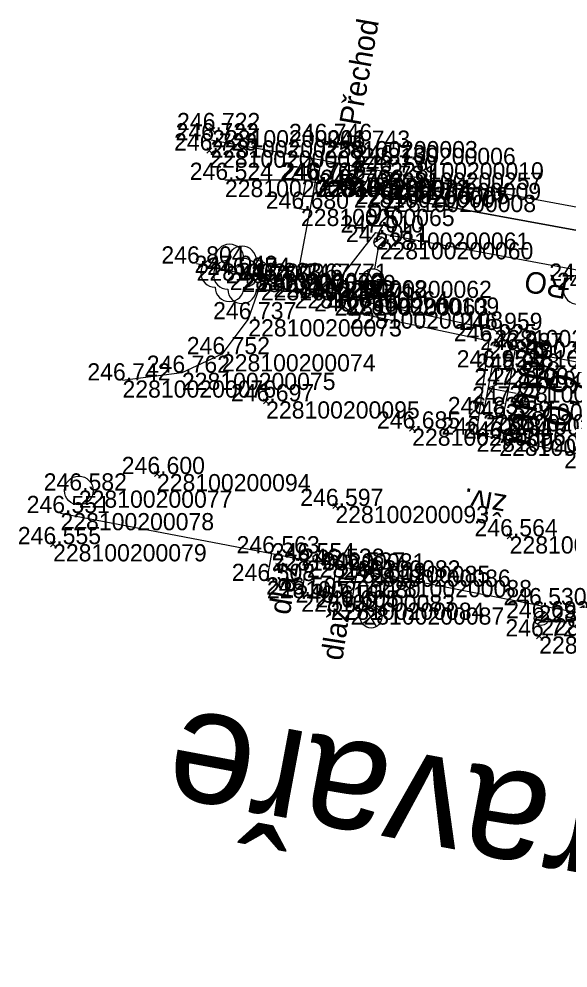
# Model space of a CAD drawing. Extents: x -489477 to -488834, y -1088874 to -1088756.
# Drawn here: x -489210.7 to -489172.4, y -1088873.7 to -1088807.5 of the extents above; entities that cross this region are included whole.
import ezdxf

# ---------------------------------------------------------------- set-up
doc = ezdxf.new("R2010")
doc.units = 0
for name, color, linetype in [('Vrstva 1', 7, 'Continuous'), ('Vrstva 12', 7, 'Continuous'), ('Vrstva 14', 7, 'Continuous'), ('Vrstva 16', 7, 'Continuous'), ('Vrstva 17', 7, 'Continuous'), ('Vrstva 23', 7, 'Continuous'), ('Vrstva 25', 7, 'Continuous'), ('Vrstva 36', 7, 'Continuous'), ('Vrstva 4', 7, 'Continuous'), ('Vrstva 43', 7, 'Continuous'), ('Vrstva 49', 7, 'Continuous'), ('Vrstva 50', 7, 'Continuous'), ('Vrstva 51', 7, 'Continuous'), ('Vrstva 60', 7, 'Continuous'), ('Vrstva 61', 7, 'Continuous')]:
    doc.layers.add(name, color=color, linetype=linetype)

msp = doc.modelspace()

# ---------------------------------------------------------------- linework, layer by layer
at = {"layer": 'Vrstva 1'}
msp.add_lwpolyline([(-489069.54, -1088836.646), (-489079.744, -1088835.745), (-489092.96, -1088834.275), (-489107.116, -1088832.285), (-489121.051, -1088829.933), (-489135.033, -1088827.388), (-489147.694, -1088825.064), (-489168.943, -1088821.148), (-489184.879, -1088818.208), (-489197.298, -1088815.961)], dxfattribs=at)
at = {"layer": 'Vrstva 12'}
msp.add_line((-489176.005, -1088833.62), (-489177.97, -1088833.248), dxfattribs=at)
for points in [[(-489176.316, -1088832.043), (-489177.696, -1088831.8), (-489178.314, -1088835.061), (-489176.925, -1088835.313), (-489176.725, -1088834.325), (-489176.475, -1088833.048), (-489176.316, -1088832.043)], [(-489177.423, -1088833.046), (-489177.97, -1088833.248), (-489177.535, -1088833.636)]]:
    msp.add_lwpolyline(points, dxfattribs=at)
at = {"layer": 'Vrstva 14'}
msp.add_lwpolyline([(-489187.318, -1088819.458), (-489185.323, -1088819.766), (-489169.302, -1088822.686), (-489155.292, -1088825.292), (-489153.303, -1088825.681), (-489149.813, -1088826.322), (-489147.827, -1088826.686), (-489135.3, -1088829.033), (-489121.345, -1088831.585), (-489107.306, -1088833.925), (-489093.168, -1088835.915), (-489080.034, -1088837.349), (-489069.629, -1088838.273)], dxfattribs=at)
at = {"layer": 'Vrstva 16'}
for points in [[(-489169.302, -1088822.686), (-489185.323, -1088819.766), (-489187.318, -1088819.458), (-489187.195, -1088819.208), (-489189.849, -1088818.713), (-489189.998, -1088818.713), (-489191.448, -1088826.485), (-489188.658, -1088826.988), (-489188.408, -1088825.755), (-489185.794, -1088822.393), (-489168.742, -1088825.545)], [(-489169.396, -1088838.257), (-489177.179, -1088836.771), (-489178.765, -1088836.485), (-489177.893, -1088829.979), (-489187.632, -1088827.897), (-489188.658, -1088826.988), (-489191.448, -1088826.485), (-489193.797, -1088825.924), (-489194.677, -1088828.441), (-489196.517, -1088830.877), (-489199.306, -1088832.173), (-489203.448, -1088832.708)], [(-489207.771, -1088841.957), (-489193.044, -1088844.767), (-489190.594, -1088845.255), (-489188.527, -1088845.637), (-489187.095, -1088845.9), (-489174.443, -1088848.384), (-489164.096, -1088850.294)], [(-489193.374, -1088846.695), (-489193.044, -1088844.767), (-489190.594, -1088845.255), (-489190.979, -1088847.638)], [(-489188.928, -1088848.205), (-489188.527, -1088845.637), (-489187.095, -1088845.9), (-489187.543, -1088848.539)]]:
    msp.add_lwpolyline(points, dxfattribs=at)
at = {"layer": 'Vrstva 17'}
msp.add_line((-489198.284, -1088824.555), (-489192.926, -1088825.715), dxfattribs=at)
msp.add_lwpolyline([(-489187.894, -1088826.922), (-489177.514, -1088829.188), (-489176.061, -1088830.595)], dxfattribs=at)
at = {"layer": 'Vrstva 23'}
msp.add_lwpolyline([(-489169.396, -1088838.257), (-489177.179, -1088836.771), (-489176.925, -1088835.313), (-489176.725, -1088834.325), (-489176.475, -1088833.048), (-489176.316, -1088832.043), (-489176.061, -1088830.595), (-489169.904, -1088831.752)], dxfattribs=at)
at = {"layer": 'Vrstva 25'}
for p, q in [((-489185.328, -1088822.714), (-489185.911, -1088823.115)), ((-489185.861, -1088824.931), (-489185.589, -1088823.456)), ((-489185.119, -1088823.055), (-489185.665, -1088823.431)), ((-489185.404, -1088825.211), (-489186.591, -1088826.123)), ((-489185.606, -1088826.305), (-489186.389, -1088825.029)), ((-489185.421, -1088846.279), (-489186.008, -1088846.674)), ((-489185.215, -1088846.622), (-489185.765, -1088846.992)), ((-489185.978, -1088848.49), (-489185.689, -1088847.019)), ((-489185.524, -1088848.776), (-489186.721, -1088849.674)), ((-489185.738, -1088849.867), (-489186.507, -1088848.583))]:
    msp.add_line(p, q, dxfattribs=at)
for centre, radius in [((-489185.516, -1088823.063), 0.4), ((-489185.997, -1088825.667), 0.749), ((-489185.612, -1088846.626), 0.4), ((-489186.122, -1088849.225), 0.749)]:
    msp.add_circle(centre, radius, dxfattribs=at)
at = {"layer": 'Vrstva 36'}
for p, q in [((-489173.967, -1088848.888), (-489174.736, -1088849.405)), ((-489173.764, -1088849.203), (-489174.523, -1088849.713))]:
    msp.add_line(p, q, dxfattribs=at)
msp.add_circle((-489174.252, -1088849.295), 0.5, dxfattribs=at)
at = {"layer": 'Vrstva 4'}
for points in [[(-489189.849, -1088818.713), (-489187.195, -1088819.208), (-489186.743, -1088816.479), (-489189.39, -1088816.011), (-489189.849, -1088818.713)], [(-489196.307, -1088818.721), (-489189.998, -1088818.713), (-489189.849, -1088818.713)]]:
    msp.add_lwpolyline(points, dxfattribs=at)
at = {"layer": 'Vrstva 43'}
msp.add_circle((-489206.492, -1088840.386), 1, dxfattribs=at)
at = {"layer": 'Vrstva 49'}
for p, q in [((-489197.372, -1088815.073), (-489197.018, -1088815.427)), ((-489197.372, -1088815.427), (-489197.018, -1088815.073)), ((-489197.578, -1088816.495), (-489197.224, -1088816.849)), ((-489197.578, -1088816.849), (-489197.224, -1088816.495)), ((-489184.963, -1088817.315), (-489184.609, -1088817.669)), ((-489184.963, -1088817.669), (-489184.609, -1088817.315)), ((-489185.15, -1088818.748), (-489184.796, -1088819.102)), ((-489185.15, -1088819.102), (-489184.796, -1088818.748)), ((-489193.612, -1088833.988), (-489193.258, -1088834.342)), ((-489193.612, -1088834.342), (-489193.258, -1088833.988)), ((-489183.429, -1088835.887), (-489183.075, -1088836.241)), ((-489183.429, -1088836.241), (-489183.075, -1088835.887)), ((-489201.225, -1088839.06), (-489200.871, -1088839.414)), ((-489201.225, -1088839.414), (-489200.871, -1088839.06)), ((-489188.784, -1088841.285), (-489188.43, -1088841.639)), ((-489188.784, -1088841.639), (-489188.43, -1088841.285)), ((-489176.634, -1088843.403), (-489176.28, -1088843.757)), ((-489176.634, -1088843.757), (-489176.28, -1088843.403)), ((-489208.464, -1088843.95), (-489208.11, -1088844.304)), ((-489208.464, -1088844.304), (-489208.11, -1088843.95)), ((-489174.575, -1088850.385), (-489174.221, -1088850.739)), ((-489174.575, -1088850.739), (-489174.221, -1088850.385))]:
    msp.add_line(p, q, dxfattribs=at)
at = {"layer": 'Vrstva 50'}
for p, q in [((-489196.045, -1088825.209), (-489195.903, -1088825.209)), ((-489195.17, -1088825.343), (-489195.028, -1088825.343))]:
    msp.add_line(p, q, dxfattribs=at)
for centre, start, end in [((-489195.985, -1088824.207), 0, 180), ((-489195.11, -1088824.341), 0, 180), ((-489196.985, -1088825.207), 90, 270), ((-489194.985, -1088825.207), 270, 90), ((-489196.11, -1088825.341), 90, 270), ((-489194.11, -1088825.341), 270, 90), ((-489171.713, -1088826.394), 90, 270), ((-489195.985, -1088826.207), 180, 0), ((-489195.11, -1088826.341), 180, 0)]:
    msp.add_arc(centre, 1, start, end, dxfattribs=at)
at = {"layer": 'Vrstva 51'}
msp.add_line((-489191.497, -1088820.65), (-489190.513, -1088820.828), dxfattribs=at)
msp.add_lwpolyline([(-489191.005, -1088820.739), (-489190.649, -1088818.771), (-489189.665, -1088818.949), (-489190.337, -1088817.049), (-489191.633, -1088818.593), (-489190.649, -1088818.771)], dxfattribs=at)
at = {"layer": 'Vrstva 60'}
for p, q in [((-489197.195, -1088815.25), (-489197.195, -1088815.25)), ((-489197.298, -1088815.961), (-489197.298, -1088815.961)), ((-489189.39, -1088816.011), (-489189.39, -1088816.011)), ((-489197.401, -1088816.672), (-489197.401, -1088816.672)), ((-489186.743, -1088816.479), (-489186.743, -1088816.479)), ((-489184.786, -1088817.492), (-489184.786, -1088817.492)), ((-489184.879, -1088818.208), (-489184.879, -1088818.208)), ((-489196.307, -1088818.721), (-489196.307, -1088818.721)), ((-489189.998, -1088818.713), (-489189.998, -1088818.713)), ((-489189.849, -1088818.713), (-489189.849, -1088818.713)), ((-489184.973, -1088818.925), (-489184.973, -1088818.925)), ((-489187.318, -1088819.458), (-489187.318, -1088819.458)), ((-489187.195, -1088819.208), (-489187.195, -1088819.208)), ((-489185.323, -1088819.766), (-489185.323, -1088819.766)), ((-489191.005, -1088820.739), (-489191.005, -1088820.739)), ((-489185.794, -1088822.393), (-489185.794, -1088822.393)), ((-489185.516, -1088823.063), (-489185.516, -1088823.063)), ((-489198.284, -1088824.555), (-489198.284, -1088824.555)), ((-489195.974, -1088825.209), (-489195.974, -1088825.209)), ((-489195.099, -1088825.343), (-489195.099, -1088825.343)), ((-489193.797, -1088825.924), (-489193.797, -1088825.924)), ((-489192.926, -1088825.715), (-489192.926, -1088825.715)), ((-489188.408, -1088825.755), (-489188.408, -1088825.755)), ((-489191.448, -1088826.485), (-489191.448, -1088826.485)), ((-489187.894, -1088826.922), (-489187.894, -1088826.922)), ((-489188.658, -1088826.988), (-489188.658, -1088826.988)), ((-489187.632, -1088827.897), (-489187.632, -1088827.897)), ((-489194.677, -1088828.441), (-489194.677, -1088828.441)), ((-489177.514, -1088829.188), (-489177.514, -1088829.188)), ((-489177.893, -1088829.979), (-489177.893, -1088829.979)), ((-489196.517, -1088830.877), (-489196.517, -1088830.877)), ((-489176.061, -1088830.595), (-489176.061, -1088830.595)), ((-489199.306, -1088832.173), (-489199.306, -1088832.173)), ((-489177.696, -1088831.8), (-489177.696, -1088831.8)), ((-489176.316, -1088832.043), (-489176.316, -1088832.043)), ((-489203.448, -1088832.708), (-489203.448, -1088832.708)), ((-489176.475, -1088833.048), (-489176.475, -1088833.048)), ((-489193.435, -1088834.165), (-489193.435, -1088834.165)), ((-489176.725, -1088834.325), (-489176.725, -1088834.325)), ((-489178.314, -1088835.061), (-489178.314, -1088835.061)), ((-489176.925, -1088835.313), (-489176.925, -1088835.313)), ((-489183.252, -1088836.064), (-489183.252, -1088836.064)), ((-489178.765, -1088836.485), (-489178.765, -1088836.485)), ((-489177.179, -1088836.771), (-489177.179, -1088836.771)), ((-489201.048, -1088839.237), (-489201.048, -1088839.237)), ((-489206.492, -1088840.386), (-489206.492, -1088840.386)), ((-489188.607, -1088841.462), (-489188.607, -1088841.462)), ((-489207.771, -1088841.957), (-489207.771, -1088841.957)), ((-489208.287, -1088844.127), (-489208.287, -1088844.127)), ((-489176.457, -1088843.58), (-489176.457, -1088843.58)), ((-489193.044, -1088844.767), (-489193.044, -1088844.767)), ((-489190.594, -1088845.255), (-489190.594, -1088845.255)), ((-489188.527, -1088845.637), (-489188.527, -1088845.637)), ((-489187.095, -1088845.9), (-489187.095, -1088845.9)), ((-489193.374, -1088846.695), (-489193.374, -1088846.695)), ((-489185.612, -1088846.626), (-489185.612, -1088846.626)), ((-489190.979, -1088847.638), (-489190.979, -1088847.638)), ((-489188.928, -1088848.205), (-489188.928, -1088848.205)), ((-489187.543, -1088848.539), (-489187.543, -1088848.539)), ((-489174.443, -1088848.384), (-489174.443, -1088848.384)), ((-489174.252, -1088849.295), (-489174.252, -1088849.295)), ((-489174.398, -1088850.562), (-489174.398, -1088850.562))]:
    msp.add_line(p, q, dxfattribs=at)

# ---------------------------------------------------------------- texts
at = {"layer": 'Vrstva 12'}
for s, p in [('rampa', (-489175.062, -1088837.372)), ('0,9', (-489172.292, -1088836.093))]:
    msp.add_text(s, height=2, rotation=79.269, dxfattribs=at).set_placement(p)
at = {"layer": 'Vrstva 16'}
for s, rotation, p in [('živ.', 170.01125, (-489176.602, -1088840.719)), ('dlaž.', 80.28727, (-489191.787, -1088849.112)), ('dlaž.', 81.12479, (-489188.13, -1088852.298))]:
    msp.add_text(s, height=1.5, rotation=rotation, dxfattribs=at).set_placement(p)
at = {"layer": 'Vrstva 23'}
msp.add_text('žst.Kravaře', height=8, rotation=169.39925, dxfattribs=at).set_placement((-489146.368, -1088865.517))
at = {"layer": 'Vrstva 25'}
for s, p in [('S6', (-489183.889, -1088820.717)), ('RO', (-489172.303, -1088825.575))]:
    msp.add_text(s, height=1.5, rotation=169.52729, dxfattribs=at).set_placement(p)
at = {"layer": 'Vrstva 4'}
msp.add_text('Přechod', height=1.5, rotation=79.9735, dxfattribs=at).set_placement((-489186.868, -1088814.997))
at = {"layer": 'Vrstva 60'}
for s, p in [('228100200001', (-489197.195, -1088816.45)), ('228100200256', (-489197.298, -1088817.161)), ('228100200003', (-489189.39, -1088817.211)), ('228100200002', (-489197.401, -1088817.872)), ('228100200006', (-489186.743, -1088817.679)), ('228100200010', (-489184.786, -1088818.692)), ('228100200257', (-489184.879, -1088819.408)), ('228100200066', (-489196.307, -1088819.921)), ('228100200072', (-489189.998, -1088819.913)), ('228100200004', (-489189.849, -1088819.913)), ('228100200009', (-489184.973, -1088820.125)), ('228100200007', (-489187.318, -1088820.658)), ('228100200005', (-489187.195, -1088820.408)), ('228100200008', (-489185.323, -1088820.966)), ('228100200065', (-489191.005, -1088821.939)), ('228100200061', (-489185.794, -1088823.593)), ('228100200060', (-489185.516, -1088824.263)), ('228100200067', (-489198.284, -1088825.755)), ('228100200070', (-489195.974, -1088826.409)), ('228100200069', (-489195.099, -1088826.543)), ('228100200071', (-489193.797, -1088827.124)), ('228100200068', (-489192.926, -1088826.915)), ('228100200062', (-489188.408, -1088826.955)), ('228100200064', (-489191.448, -1088827.685)), ('228100200109', (-489187.894, -1088828.122)), ('228100200063', (-489188.658, -1088828.188)), ('228100200108', (-489187.632, -1088829.097)), ('228100200073', (-489194.677, -1088829.641)), ('228100200106', (-489177.514, -1088830.388)), ('228100200107', (-489177.893, -1088831.179)), ('228100200074', (-489196.517, -1088832.077)), ('228100200105', (-489176.061, -1088831.795)), ('228100200075', (-489199.306, -1088833.373)), ('228100200101', (-489177.696, -1088833)), ('228100200102', (-489176.316, -1088833.243)), ('228100200076', (-489203.448, -1088833.908)), ('228100200103', (-489176.475, -1088834.248)), ('228100200095', (-489193.435, -1088835.365)), ('228100200104', (-489176.725, -1088835.525)), ('228100200099', (-489178.314, -1088836.261)), ('228100200100', (-489176.925, -1088836.513)), ('228100200096', (-489183.252, -1088837.264)), ('228100200097', (-489178.765, -1088837.685)), ('228100200098', (-489177.179, -1088837.971)), ('228100200094', (-489201.048, -1088840.437)), ('228100200077', (-489206.492, -1088841.586)), ('228100200093', (-489188.607, -1088842.662)), ('228100200078', (-489207.771, -1088843.157)), ('228100200079', (-489208.287, -1088845.327)), ('228100200092', (-489176.457, -1088844.78)), ('228100200081', (-489193.044, -1088845.967)), ('228100200082', (-489190.594, -1088846.455)), ('228100200085', (-489188.527, -1088846.837)), ('228100200086', (-489187.095, -1088847.1)), ('228100200080', (-489193.374, -1088847.895)), ('228100200088', (-489185.612, -1088847.826)), ('228100200083', (-489190.979, -1088848.838)), ('228100200084', (-489188.928, -1088849.405)), ('228100200087', (-489187.543, -1088849.739)), ('228100200091', (-489174.443, -1088849.584)), ('228100200090', (-489174.252, -1088850.495)), ('228100200089', (-489174.398, -1088851.762))]:
    msp.add_text(s, height=1.2, dxfattribs=at).set_placement(p)
at = {"layer": 'Vrstva 61'}
for s, p in [('246.722', (-489199.643, -1088815.25)), ('246.722', (-489199.746, -1088815.961)), ('246.746', (-489191.842, -1088816.011)), ('246.723', (-489199.853, -1088816.672)), ('246.743', (-489189.195, -1088816.479)), ('246.730', (-489187.237, -1088817.492)), ('246.730', (-489187.33, -1088818.208)), ('246.524', (-489198.758, -1088818.721)), ('246.762', (-489192.446, -1088818.713)), ('246.746', (-489192.301, -1088818.713)), ('246.705', (-489189.774, -1088819.458)), ('246.732', (-489189.643, -1088819.208)), ('246.731', (-489187.33, -1088818.925)), ('246.988', (-489187.777, -1088819.766)), ('246.680', (-489193.456, -1088820.739)), ('247.010', (-489188.245, -1088822.393)), ('247.011', (-489187.873, -1088823.063)), ('246.804', (-489200.735, -1088824.555)), ('247.049', (-489198.428, -1088825.209)), ('246.974', (-489197.55, -1088825.343)), ('246.776', (-489196.249, -1088825.924)), ('246.823', (-489195.378, -1088825.715)), ('246.771', (-489190.765, -1088825.755)), ('246.920', (-489173.689, -1088825.752)), ('246.720', (-489193.899, -1088826.485)), ('246.994', (-489173.153, -1088826.396)), ('246.754', (-489191.109, -1088826.988)), ('246.782', (-489190.342, -1088826.922)), ('246.768', (-489190.086, -1088827.897)), ('246.737', (-489197.129, -1088828.441)), ('246.959', (-489179.968, -1088829.188)), ('246.925', (-489180.349, -1088829.979)), ('246.987', (-489178.513, -1088830.595)), ('246.752', (-489198.965, -1088830.877)), ('246.953', (-489180.148, -1088831.8)), ('246.978', (-489178.77, -1088832.043)), ('246.742', (-489205.896, -1088832.708)), ('246.762', (-489201.754, -1088832.173)), ('247.772', (-489178.923, -1088833.048)), ('246.697', (-489195.887, -1088834.165)), ('247.771', (-489179.082, -1088834.325)), ('246.839', (-489180.768, -1088835.061)), ('246.829', (-489179.379, -1088835.313)), ('246.685', (-489185.708, -1088836.064)), ('246.702', (-489181.213, -1088836.485)), ('246.664', (-489179.63, -1088836.771)), ('246.600', (-489203.499, -1088839.237)), ('246.696', (-489172.661, -1088838.838)), ('246.582', (-489208.94, -1088840.386)), ('246.551', (-489210.128, -1088841.957)), ('246.597', (-489191.059, -1088841.462)), ('246.564', (-489178.908, -1088843.58)), ('246.555', (-489210.743, -1088844.127)), ('246.563', (-489195.496, -1088844.767)), ('246.554', (-489193.045, -1088845.255)), ('246.538', (-489190.981, -1088845.637)), ('246.537', (-489189.547, -1088845.9)), ('246.508', (-489195.828, -1088846.695)), ('246.619', (-489188.066, -1088846.626)), ('246.505', (-489193.435, -1088847.638)), ('246.616', (-489191.38, -1088848.205)), ('246.605', (-489189.999, -1088848.539)), ('246.530', (-489176.894, -1088848.384)), ('246.692', (-489176.7, -1088849.295)), ('246.721', (-489176.755, -1088850.562))]:
    msp.add_text(s, height=1.2, dxfattribs=at).set_placement(p)

doc.saveas('drawing.dxf')
